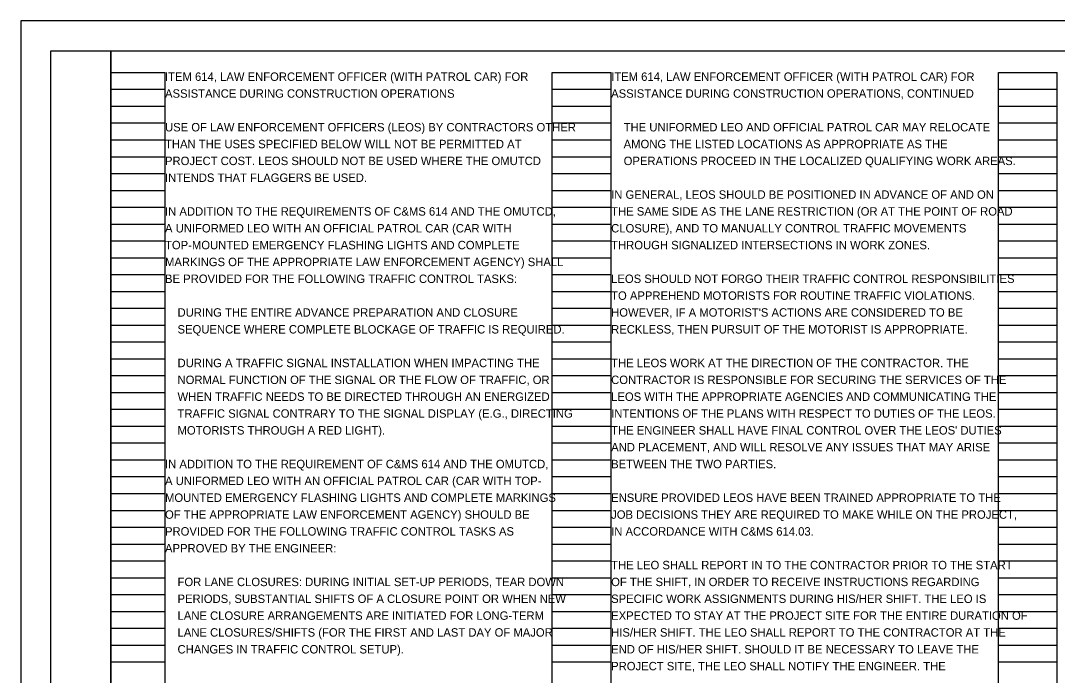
# Model space of a CAD drawing. Extents: x 0 to 34, y 0 to 22.
# Drawn here: x 0 to 17.24, y 11.12 to 22 of the extents above; entities that cross this region are included whole.
import ezdxf

# ---------------------------------------------------------------- set-up
doc = ezdxf.new("R2010")
doc.units = 0
for name, color, linetype in [('SH_Border', 7, 'Continuous'), ('SH_Cut_Line', 7, 'Continuous'), ('SH_Data', 7, 'Continuous'), ('SH_Text', 7, 'Continuous')]:
    doc.layers.add(name, color=color, linetype=linetype)

msp = doc.modelspace()

# ---------------------------------------------------------------- linework, layer by layer
at = {"layer": 'SH_Border'}
for points in [[(0.5, 21.5), (1.5, 21.5), (1.5, 0.5), (0.5, 0.5)], [(1.5, 21.5), (33.5, 21.5), (33.5, 0.5), (1.5, 0.5)]]:
    msp.add_lwpolyline(points, close=True, dxfattribs=at)
at = {"layer": 'SH_Cut_Line'}
msp.add_lwpolyline([(0, 0), (34, 0), (34, 22), (0, 22)], close=True, dxfattribs=at)
at = {"layer": 'SH_Data'}
for p, q in [((1.5, 0.98), (1.5, 21.14)), ((1.5, 21.14), (2.4, 21.14)), ((2.4, 0.98), (2.4, 21.14)), ((8.84, 0.98), (8.84, 21.14)), ((8.84, 21.14), (9.82, 21.14)), ((9.82, 0.98), (9.82, 21.14)), ((16.26, 0.98), (16.26, 21.14)), ((16.26, 21.14), (17.24, 21.14)), ((17.24, 0.98), (17.24, 21.14)), ((1.5, 20.86), (2.4, 20.86)), ((8.84, 20.86), (9.82, 20.86)), ((16.26, 20.86), (17.24, 20.86)), ((1.5, 20.58), (2.4, 20.58)), ((8.84, 20.58), (9.82, 20.58)), ((16.26, 20.58), (17.24, 20.58)), ((1.5, 20.3), (2.4, 20.3)), ((8.84, 20.3), (9.82, 20.3)), ((16.26, 20.3), (17.24, 20.3)), ((1.5, 20.02), (2.4, 20.02)), ((8.84, 20.02), (9.82, 20.02)), ((16.26, 20.02), (17.24, 20.02)), ((1.5, 19.74), (2.4, 19.74)), ((8.84, 19.74), (9.82, 19.74)), ((16.26, 19.74), (17.24, 19.74)), ((1.5, 19.46), (2.4, 19.46)), ((8.84, 19.46), (9.82, 19.46)), ((16.26, 19.46), (17.24, 19.46)), ((1.5, 19.18), (2.4, 19.18)), ((8.84, 19.18), (9.82, 19.18)), ((16.26, 19.18), (17.24, 19.18)), ((1.5, 18.9), (2.4, 18.9)), ((8.84, 18.9), (9.82, 18.9)), ((16.26, 18.9), (17.24, 18.9)), ((1.5, 18.62), (2.4, 18.62)), ((8.84, 18.62), (9.82, 18.62)), ((16.26, 18.62), (17.24, 18.62)), ((1.5, 18.34), (2.4, 18.34)), ((8.84, 18.34), (9.82, 18.34)), ((16.26, 18.34), (17.24, 18.34)), ((1.5, 18.06), (2.4, 18.06)), ((8.84, 18.06), (9.82, 18.06)), ((16.26, 18.06), (17.24, 18.06)), ((1.5, 17.78), (2.4, 17.78)), ((8.84, 17.78), (9.82, 17.78)), ((16.26, 17.78), (17.24, 17.78)), ((1.5, 17.5), (2.4, 17.5)), ((8.84, 17.5), (9.82, 17.5)), ((16.26, 17.5), (17.24, 17.5)), ((1.5, 17.22), (2.4, 17.22)), ((8.84, 17.22), (9.82, 17.22)), ((16.26, 17.22), (17.24, 17.22)), ((1.5, 16.94), (2.4, 16.94)), ((8.84, 16.94), (9.82, 16.94)), ((16.26, 16.94), (17.24, 16.94)), ((1.5, 16.66), (2.4, 16.66)), ((8.84, 16.66), (9.82, 16.66)), ((16.26, 16.66), (17.24, 16.66)), ((1.5, 16.38), (2.4, 16.38)), ((8.84, 16.38), (9.82, 16.38)), ((16.26, 16.38), (17.24, 16.38)), ((1.5, 16.1), (2.4, 16.1)), ((8.84, 16.1), (9.82, 16.1)), ((16.26, 16.1), (17.24, 16.1)), ((1.5, 15.82), (2.4, 15.82)), ((8.84, 15.82), (9.82, 15.82)), ((16.26, 15.82), (17.24, 15.82)), ((1.5, 15.54), (2.4, 15.54)), ((8.84, 15.54), (9.82, 15.54)), ((16.26, 15.54), (17.24, 15.54)), ((1.5, 15.26), (2.4, 15.26)), ((8.84, 15.26), (9.82, 15.26)), ((16.26, 15.26), (17.24, 15.26)), ((1.5, 14.98), (2.4, 14.98)), ((8.84, 14.98), (9.82, 14.98)), ((16.26, 14.98), (17.24, 14.98)), ((1.5, 14.7), (2.4, 14.7)), ((8.84, 14.7), (9.82, 14.7)), ((16.26, 14.7), (17.24, 14.7)), ((1.5, 14.42), (2.4, 14.42)), ((8.84, 14.42), (9.82, 14.42)), ((16.26, 14.42), (17.24, 14.42)), ((1.5, 14.14), (2.4, 14.14)), ((8.84, 14.14), (9.82, 14.14)), ((16.26, 14.14), (17.24, 14.14)), ((1.5, 13.86), (2.4, 13.86)), ((8.84, 13.86), (9.82, 13.86)), ((16.26, 13.86), (17.24, 13.86)), ((1.5, 13.58), (2.4, 13.58)), ((8.84, 13.58), (9.82, 13.58)), ((16.26, 13.58), (17.24, 13.58)), ((1.5, 13.3), (2.4, 13.3)), ((8.84, 13.3), (9.82, 13.3)), ((16.26, 13.3), (17.24, 13.3)), ((1.5, 13.02), (2.4, 13.02)), ((8.84, 13.02), (9.82, 13.02)), ((16.26, 13.02), (17.24, 13.02)), ((1.5, 12.74), (2.4, 12.74)), ((8.84, 12.74), (9.82, 12.74)), ((16.26, 12.74), (17.24, 12.74)), ((1.5, 12.46), (2.4, 12.46)), ((8.84, 12.46), (9.82, 12.46)), ((16.26, 12.46), (17.24, 12.46)), ((1.5, 12.18), (2.4, 12.18)), ((8.84, 12.18), (9.82, 12.18)), ((16.26, 12.18), (17.24, 12.18)), ((1.5, 11.9), (2.4, 11.9)), ((8.84, 11.9), (9.82, 11.9)), ((16.26, 11.9), (17.24, 11.9)), ((1.5, 11.62), (2.4, 11.62)), ((8.84, 11.62), (9.82, 11.62)), ((16.26, 11.62), (17.24, 11.62)), ((1.5, 11.34), (2.4, 11.34)), ((8.84, 11.34), (9.82, 11.34)), ((16.26, 11.34), (17.24, 11.34))]:
    msp.add_line(p, q, dxfattribs=at)

# ---------------------------------------------------------------- texts
at = {"layer": 'SH_Text'}
for s, p in [('ITEM 614, LAW ENFORCEMENT OFFICER (WITH PATROL CAR) FOR', (2.4, 21)), ('ITEM 614, LAW ENFORCEMENT OFFICER (WITH PATROL CAR) FOR', (9.82, 21)), ('ASSISTANCE DURING CONSTRUCTION OPERATIONS', (2.4, 20.72)), ('ASSISTANCE DURING CONSTRUCTION OPERATIONS, CONTINUED', (9.82, 20.72)), ('USE OF LAW ENFORCEMENT OFFICERS (LEOS) BY CONTRACTORS OTHER', (2.4, 20.16)), ('    THE UNIFORMED LEO AND OFFICIAL PATROL CAR MAY RELOCATE', (9.82, 20.16)), ('THAN THE USES SPECIFIED BELOW WILL NOT BE PERMITTED AT', (2.4, 19.88)), ('    AMONG THE LISTED LOCATIONS AS APPROPRIATE AS THE', (9.82, 19.88)), ('PROJECT COST. LEOS SHOULD NOT BE USED WHERE THE OMUTCD', (2.4, 19.6)), ('    OPERATIONS PROCEED IN THE LOCALIZED QUALIFYING WORK AREAS.', (9.82, 19.6)), ('INTENDS THAT FLAGGERS BE USED.', (2.4, 19.32)), ('IN GENERAL, LEOS SHOULD BE POSITIONED IN ADVANCE OF AND ON', (9.82, 19.04)), ('IN ADDITION TO THE REQUIREMENTS OF C&MS 614 AND THE OMUTCD,', (2.4, 18.76)), ('THE SAME SIDE AS THE LANE RESTRICTION (OR AT THE POINT OF ROAD', (9.82, 18.76)), ('A UNIFORMED LEO WITH AN OFFICIAL PATROL CAR (CAR WITH', (2.4, 18.48)), ('CLOSURE), AND TO MANUALLY CONTROL TRAFFIC MOVEMENTS', (9.82, 18.48)), ('TOP-MOUNTED EMERGENCY FLASHING LIGHTS AND COMPLETE', (2.4, 18.2)), ('THROUGH SIGNALIZED INTERSECTIONS IN WORK ZONES.', (9.82, 18.2)), ('MARKINGS OF THE APPROPRIATE LAW ENFORCEMENT AGENCY) SHALL', (2.4, 17.92)), ('BE PROVIDED FOR THE FOLLOWING TRAFFIC CONTROL TASKS:', (2.4, 17.64)), ('LEOS SHOULD NOT FORGO THEIR TRAFFIC CONTROL RESPONSIBILITIES', (9.82, 17.64)), ('TO APPREHEND MOTORISTS FOR ROUTINE TRAFFIC VIOLATIONS.', (9.82, 17.36)), ('    DURING THE ENTIRE ADVANCE PREPARATION AND CLOSURE', (2.4, 17.08)), ("HOWEVER, IF A MOTORIST'S ACTIONS ARE CONSIDERED TO BE", (9.82, 17.08)), ('    SEQUENCE WHERE COMPLETE BLOCKAGE OF TRAFFIC IS REQUIRED.', (2.4, 16.8)), ('RECKLESS, THEN PURSUIT OF THE MOTORIST IS APPROPRIATE.', (9.82, 16.8)), ('    DURING A TRAFFIC SIGNAL INSTALLATION WHEN IMPACTING THE', (2.4, 16.24)), ('THE LEOS WORK AT THE DIRECTION OF THE CONTRACTOR. THE', (9.82, 16.24)), ('    NORMAL FUNCTION OF THE SIGNAL OR THE FLOW OF TRAFFIC, OR', (2.4, 15.96)), ('CONTRACTOR IS RESPONSIBLE FOR SECURING THE SERVICES OF THE', (9.82, 15.96)), ('    WHEN TRAFFIC NEEDS TO BE DIRECTED THROUGH AN ENERGIZED', (2.4, 15.68)), ('LEOS WITH THE APPROPRIATE AGENCIES AND COMMUNICATING THE', (9.82, 15.68)), ('    TRAFFIC SIGNAL CONTRARY TO THE SIGNAL DISPLAY (E.G., DIRECTING', (2.4, 15.4)), ('INTENTIONS OF THE PLANS WITH RESPECT TO DUTIES OF THE LEOS.', (9.82, 15.4)), ('    MOTORISTS THROUGH A RED LIGHT).', (2.4, 15.12)), ("THE ENGINEER SHALL HAVE FINAL CONTROL OVER THE LEOS' DUTIES", (9.82, 15.12)), ('AND PLACEMENT, AND WILL RESOLVE ANY ISSUES THAT MAY ARISE', (9.82, 14.84)), ('IN ADDITION TO THE REQUIREMENT OF C&MS 614 AND THE OMUTCD,', (2.4, 14.56)), ('BETWEEN THE TWO PARTIES.', (9.82, 14.56)), ('A UNIFORMED LEO WITH AN OFFICIAL PATROL CAR (CAR WITH TOP-', (2.4, 14.28)), ('MOUNTED EMERGENCY FLASHING LIGHTS AND COMPLETE MARKINGS', (2.4, 14)), ('ENSURE PROVIDED LEOS HAVE BEEN TRAINED APPROPRIATE TO THE', (9.82, 14)), ('OF THE APPROPRIATE LAW ENFORCEMENT AGENCY) SHOULD BE', (2.4, 13.72)), ('JOB DECISIONS THEY ARE REQUIRED TO MAKE WHILE ON THE PROJECT,', (9.82, 13.72)), ('PROVIDED FOR THE FOLLOWING TRAFFIC CONTROL TASKS AS', (2.4, 13.44)), ('IN ACCORDANCE WITH C&MS 614.03.', (9.82, 13.44)), ('APPROVED BY THE ENGINEER:', (2.4, 13.16)), ('THE LEO SHALL REPORT IN TO THE CONTRACTOR PRIOR TO THE START', (9.82, 12.88)), ('    FOR LANE CLOSURES: DURING INITIAL SET-UP PERIODS, TEAR DOWN', (2.4, 12.6)), ('OF THE SHIFT, IN ORDER TO RECEIVE INSTRUCTIONS REGARDING', (9.82, 12.6)), ('    PERIODS, SUBSTANTIAL SHIFTS OF A CLOSURE POINT OR WHEN NEW', (2.4, 12.32)), ('SPECIFIC WORK ASSIGNMENTS DURING HIS/HER SHIFT. THE LEO IS', (9.82, 12.32)), ('    LANE CLOSURE ARRANGEMENTS ARE INITIATED FOR LONG-TERM', (2.4, 12.04)), ('EXPECTED TO STAY AT THE PROJECT SITE FOR THE ENTIRE DURATION OF', (9.82, 12.04)), ('    LANE CLOSURES/SHIFTS (FOR THE FIRST AND LAST DAY OF MAJOR', (2.4, 11.76)), ('HIS/HER SHIFT. THE LEO SHALL REPORT TO THE CONTRACTOR AT THE', (9.82, 11.76)), ('    CHANGES IN TRAFFIC CONTROL SETUP).', (2.4, 11.48)), ('END OF HIS/HER SHIFT. SHOULD IT BE NECESSARY TO LEAVE THE', (9.82, 11.48)), ('PROJECT SITE, THE LEO SHALL NOTIFY THE ENGINEER. THE', (9.82, 11.2))]:
    msp.add_text(s, height=0.14, dxfattribs=at).set_placement(p)

doc.saveas('drawing.dxf')
